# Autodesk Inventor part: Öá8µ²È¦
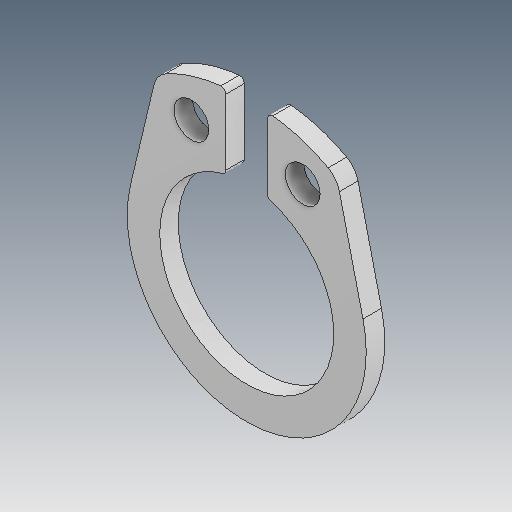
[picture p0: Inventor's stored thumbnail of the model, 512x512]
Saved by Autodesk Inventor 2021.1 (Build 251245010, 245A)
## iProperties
Created: 2021-05
Part Number: Öá8µ²È¦
Material: Ogólny
Document SubType Name: Modeling
Designer: user
Density: 1 g/cm^3
Appearance: Domyślna
Author: user
Revision Number: ÈÎºÎ
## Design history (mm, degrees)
feature "ÊäÈë1"
node "Bryła1"
